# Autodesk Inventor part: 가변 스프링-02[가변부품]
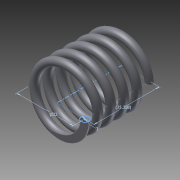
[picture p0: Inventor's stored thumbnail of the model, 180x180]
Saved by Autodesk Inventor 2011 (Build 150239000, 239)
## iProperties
Created: 2015-05
Part Number: 가변 스프링-02[가변부품]
Document SubType Name: Modeling
Designer: Administrator
Density: 7.87 g/cm^3
Mass: 18.7943 g
Surface Area: 32.7 cm^2
Volume: 2.38809 cm^3
Material: 탄소강
Author: Administrator
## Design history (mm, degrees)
sketch "스케치1"
  geometry: L1 (0, 0)-(11, 0); L2 (11, 0)-(11, 25.358); L3 (11, 25.358)-(0, 25.358); L4 (0, 25.358)-(0, 0); C1 r 1.5 at (11, 0)
  constraints: 8 end point, 2 parallel, 1 centre point, 1 coincident, 1 horizontal, 1 perpendicular
  dimensions: "d0" = 22 diameter of L2 L4; "d1" = 3 diameter of C1; "d2" = 25.35829 distance of L1.end L2.end (derived)
feature "코일1" pitch "d3" = 10; turns "d5" = 5; dims "d4" = 25.35829 (= d2), "d6" = 0, angle "d7" = 90 deg, angle "d8" = 90 deg, "d9" = 0, "d10" = 0
sketch "스케치2"
  geometry: L1 (-12.5, 0)-(-9.5, 0) reference; 1 further point
  constraints: 1 horizontal alignment
extrude "돌출1" cut sketch "스케치2" stored distance "d11" = 10; taper "d12" = 0 deg
node "작업 평면1"
sketch "스케치3"
  geometry: L1 (1.5, 0)-(-1.5, 0) reference; 1 further point
  constraints: 1 horizontal alignment
extrude "돌출2" cut sketch "스케치3" stored distance "d13" = 10; taper "d14" = 0 deg
node "솔리드1"
node "절단 모서리 투영1"
node "절단 모서리 투영2"
